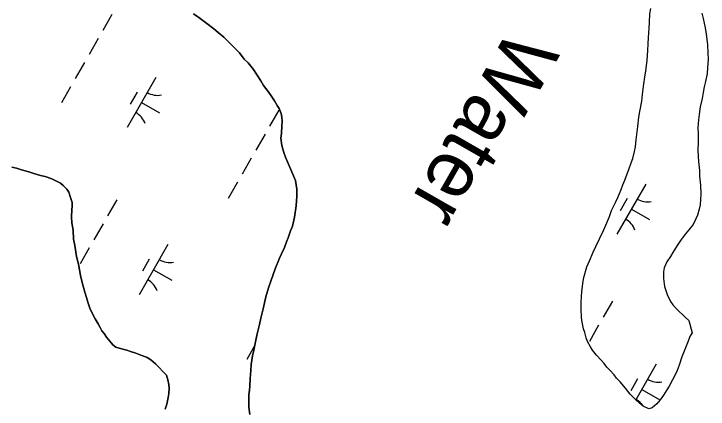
# Model space of a CAD drawing. Extents: x 3930721 to 3950824, y 220441 to 242861.
# Drawn here: x 3941538 to 3942139, y 224828 to 225170 of the extents above; entities that cross this region are included whole.
import ezdxf

# ---------------------------------------------------------------- set-up
doc = ezdxf.new("R2010")
doc.units = 0
for name, color, linetype in [('V-RIVR-IDEN', 7, 'Continuous'), ('V-TOPO-SHOR', 7, 'Continuous'), ('V-WETL-SWMP', 7, 'Continuous')]:
    doc.layers.add(name, color=color, linetype=linetype)

msp = doc.modelspace()

# ---------------------------------------------------------------- linework, layer by layer
at = {"layer": 'V-TOPO-SHOR'}
for points in [[(3941742.19, 224823.69), (3941741.55, 224829.96), (3941741.53, 224833.6), (3941741.51, 224837.25), (3941741.49, 224840.68), (3941742.08, 224844.53), (3941742.46, 224848.18), (3941742.63, 224854.85), (3941743.2, 224861.73), (3941743.58, 224866.79), (3941744.75, 224874.29), (3941745.74, 224879.35), (3941747.52, 224887.86), (3941748.7, 224893.32), (3941750.68, 224901.43), (3941751.87, 224906.9), (3941753.85, 224915), (3941755.03, 224920.07), (3941756.22, 224925.33), (3941758.6, 224933.23), (3941760.4, 224938.91), (3941764.18, 224949.65), (3941767.98, 224958.77), (3941769.78, 224962.63), (3941772.18, 224968.1), (3941774.18, 224972.97), (3941775.57, 224976.42), (3941777.56, 224982.29), (3941779.16, 224986.55), (3941780.94, 224994.25), (3941782.3, 225004.17), (3941782.87, 225012.47), (3941783.04, 225018.34), (3941781.79, 225025.81), (3941780.15, 225030.05), (3941777.48, 225035.91), (3941775.85, 225039.94), (3941773.18, 225046.2), (3941771.75, 225050.04), (3941769.89, 225056.1), (3941769.25, 225062.57), (3941769.63, 225066.62), (3941770, 225073.09), (3941770.18, 225077.34), (3941769.96, 225080.78), (3941769.34, 225084.02), (3941767.7, 225088.26), (3941766.07, 225090.88), (3941763.62, 225094.91), (3941760.76, 225099.14), (3941758.31, 225102.77), (3941754.24, 225108.21), (3941751.79, 225112.04), (3941748.12, 225117.89), (3941745.47, 225121.92), (3941740.79, 225127.56), (3941737.53, 225130.99), (3941733.25, 225136.23), (3941729.8, 225139.85), (3941726.74, 225143.07), (3941722.68, 225147.09), (3941719.83, 225149.91), (3941714.95, 225153.93), (3941711.29, 225157.15), (3941705.2, 225161.77), (3941698.29, 225166.79), (3941693.62, 225170.01)], [(3941536.31, 225037.47), (3941540.37, 225036.48), (3941544.62, 225035.28), (3941551.11, 225033.5), (3941555.36, 225032.11), (3941561.24, 225030.32), (3941565.29, 225029.32), (3941570.96, 225027.33), (3941574.01, 225025.93), (3941578.47, 225023.53), (3941580.91, 225021.52), (3941583.96, 225018.5), (3941585.79, 225015.88), (3941587.23, 225011.23), (3941588.47, 225006.79), (3941588.49, 225003.75), (3941588.3, 225000.51), (3941587.93, 224994.65), (3941588.36, 224989.39), (3941589.41, 224982.92), (3941589.85, 224975.23), (3941590.89, 224969.78), (3941592.36, 224960.27), (3941594.01, 224953.61), (3941595.89, 224943.9), (3941597.33, 224937.84), (3941599.4, 224929.36), (3941600.84, 224924.91), (3941602.28, 224920.68), (3941603.93, 224915.62)], [(3941603.93, 224915.62), (3941606.38, 224909.97), (3941608.43, 224906.34), (3941611.08, 224901.9), (3941612.71, 224898.88), (3941614.35, 224896.06), (3941616.18, 224893.64), (3941618.22, 224890.61), (3941621.07, 224886.99), (3941623.72, 224883.96), (3941626.36, 224881.96), (3941631.22, 224880.36), (3941635.88, 224879.17), (3941639.12, 224878.18), (3941643.58, 224876.59), (3941646.42, 224875.59), (3941653.52, 224872.79), (3941656.76, 224870.99), (3941660.62, 224867.57), (3941663.27, 224864.95), (3941667.74, 224860.33), (3941670.19, 224857.5), (3941671.42, 224853.67), (3941672.25, 224849.63), (3941672.47, 224846.39), (3941672.29, 224841.74), (3941671.7, 224838.29), (3941670.52, 224832.42), (3941668.93, 224828.16)]]:
    msp.add_lwpolyline(points, dxfattribs=at)
at = {"layer": 'V-WETL-SWMP'}
for p, q in [((3941623.03, 225169.54), (3941615.08, 225155.66)), ((3941693.62, 225170), (3941698.29, 225166.79)), ((3941698.29, 225166.79), (3941705.2, 225161.77)), ((3941705.2, 225161.77), (3941711.29, 225157.15)), ((3941711.29, 225157.15), (3941714.95, 225153.93)), ((3941611.11, 225148.72), (3941603.16, 225134.83)), ((3941714.95, 225153.93), (3941719.83, 225149.91)), ((3941719.83, 225149.91), (3941722.67, 225147.09)), ((3941722.67, 225147.09), (3941726.74, 225143.07)), ((3941726.74, 225143.07), (3941729.79, 225139.85)), ((3941729.79, 225139.85), (3941733.25, 225136.22)), ((3941733.25, 225136.22), (3941737.53, 225130.99)), ((3941737.53, 225130.99), (3941740.78, 225127.56)), ((3941599.18, 225127.89), (3941591.23, 225114.01)), ((3941740.78, 225127.56), (3941745.47, 225121.92)), ((3941745.47, 225121.92), (3941748.12, 225117.89)), ((3941661.01, 225115.04), (3941636.16, 225071.66)), ((3941748.12, 225117.89), (3941751.79, 225112.04)), ((3941587.25, 225107.06), (3941579.3, 225093.18)), ((3941751.79, 225112.04), (3941754.24, 225108.21)), ((3941754.24, 225108.21), (3941758.31, 225102.77)), ((3941644.87, 225102.39), (3941638.9, 225091.98)), ((3941758.31, 225102.77), (3941760.76, 225099.14)), ((3941760.76, 225099.14), (3941763.62, 225094.91)), ((3941763.62, 225094.91), (3941766.06, 225090.88)), ((3941648.58, 225093.35), (3941664.2, 225084.4)), ((3941766.06, 225090.88), (3941767.7, 225088.26)), ((3941767.38, 225086.88), (3941759.42, 225072.99)), ((3941767.7, 225088.26), (3941769.34, 225084.02)), ((3941769.34, 225084.02), (3941769.96, 225080.78)), ((3941769.96, 225080.78), (3941770.18, 225077.34)), ((3941770.18, 225077.34), (3941770, 225073.09)), ((3941770, 225073.09), (3941769.63, 225066.62)), ((3941755.45, 225066.05), (3941747.5, 225052.17)), ((3941769.63, 225066.62), (3941769.25, 225062.57)), ((3941769.25, 225062.57), (3941769.89, 225056.1)), ((3941769.89, 225056.1), (3941771.74, 225050.04)), ((3941771.74, 225050.04), (3941773.18, 225046.2)), ((3941743.52, 225045.22), (3941735.57, 225031.34)), ((3941773.18, 225046.2), (3941775.84, 225039.94)), ((3941540.37, 225036.48), (3941536.31, 225037.47)), ((3941544.62, 225035.28), (3941540.37, 225036.48)), ((3941551.1, 225033.5), (3941544.62, 225035.28)), ((3941775.84, 225039.94), (3941777.48, 225035.91)), ((3941777.48, 225035.91), (3941780.14, 225030.05)), ((3941555.36, 225032.1), (3941551.1, 225033.5)), ((3941561.24, 225030.31), (3941555.36, 225032.1)), ((3941565.29, 225029.32), (3941561.24, 225030.31)), ((3941570.96, 225027.33), (3941565.29, 225029.32)), ((3941780.14, 225030.05), (3941781.78, 225025.81)), ((3941574.01, 225025.93), (3941570.96, 225027.33)), ((3941578.47, 225023.53), (3941574.01, 225025.93)), ((3941580.91, 225021.52), (3941578.47, 225023.53)), ((3941731.59, 225024.4), (3941723.64, 225010.51)), ((3941781.78, 225025.81), (3941783.04, 225018.34)), ((3942084.88, 225022.92), (3942060.03, 224979.53)), ((3941583.96, 225018.5), (3941580.91, 225021.52)), ((3941585.79, 225015.88), (3941583.96, 225018.5)), ((3941783.04, 225018.34), (3941782.87, 225012.47)), ((3941587.23, 225011.23), (3941585.79, 225015.88)), ((3941588.47, 225006.79), (3941587.23, 225011.23)), ((3941782.87, 225012.47), (3941782.3, 225004.17)), ((3942068.74, 225010.27), (3942062.78, 224999.86)), ((3941588.49, 225003.75), (3941588.47, 225006.79)), ((3941627.21, 225009.33), (3941619.26, 224995.44)), ((3941587.93, 224994.65), (3941588.3, 225000.51)), ((3941588.3, 225000.51), (3941588.49, 225003.75)), ((3941782.3, 225004.17), (3941780.94, 224994.25)), ((3942072.46, 225001.23), (3942088.08, 224992.28)), ((3941588.36, 224989.39), (3941587.93, 224994.65)), ((3941780.94, 224994.25), (3941779.16, 224986.55)), ((3941589.41, 224982.92), (3941588.36, 224989.39)), ((3941615.29, 224988.5), (3941607.33, 224974.62)), ((3941779.16, 224986.55), (3941777.56, 224982.29)), ((3941589.85, 224975.23), (3941589.41, 224982.92)), ((3941777.56, 224982.29), (3941775.57, 224976.42)), ((3941590.89, 224969.78), (3941589.85, 224975.23)), ((3941775.57, 224976.42), (3941774.17, 224972.97)), ((3941592.36, 224960.28), (3941590.89, 224969.78)), ((3941671.48, 224970.49), (3941646.63, 224927.1)), ((3941774.17, 224972.97), (3941772.18, 224968.1)), ((3941603.36, 224967.67), (3941595.41, 224953.79)), ((3941769.78, 224962.63), (3941767.98, 224958.77)), ((3941772.18, 224968.1), (3941769.78, 224962.63)), ((3941594.01, 224953.61), (3941592.36, 224960.28)), ((3941655.34, 224957.83), (3941649.38, 224947.42)), ((3941767.98, 224958.77), (3941764.18, 224949.65)), ((3941595.88, 224943.91), (3941594.01, 224953.61)), ((3941659.06, 224948.79), (3941674.68, 224939.85)), ((3941764.18, 224949.65), (3941760.39, 224938.91)), ((3941597.33, 224937.84), (3941595.88, 224943.91)), ((3941760.39, 224938.91), (3941758.6, 224933.23)), ((3941599.4, 224929.36), (3941597.33, 224937.84)), ((3941758.6, 224933.23), (3941756.22, 224925.33)), ((3941600.84, 224924.92), (3941599.4, 224929.36)), ((3941602.28, 224920.67), (3941600.84, 224924.92)), ((3941603.92, 224915.62), (3941602.28, 224920.67)), ((3941756.22, 224925.33), (3941755.03, 224920.06)), ((3942056.06, 224921.54), (3942048.11, 224907.66)), ((3941606.38, 224909.97), (3941603.92, 224915.62)), ((3941753.84, 224915), (3941751.86, 224906.9)), ((3941755.03, 224920.06), (3941753.84, 224915)), ((3941608.42, 224906.34), (3941606.38, 224909.97)), ((3941611.08, 224901.91), (3941608.42, 224906.34)), ((3941751.86, 224906.9), (3941750.68, 224901.43)), ((3941612.71, 224898.88), (3941611.08, 224901.91)), ((3941614.35, 224896.06), (3941612.71, 224898.88)), ((3941750.68, 224901.43), (3941748.7, 224893.33)), ((3942044.13, 224900.72), (3942036.18, 224886.83)), ((3941616.18, 224893.64), (3941614.35, 224896.06)), ((3941618.22, 224890.61), (3941616.18, 224893.64)), ((3941621.07, 224886.99), (3941618.22, 224890.61)), ((3941748.7, 224893.33), (3941747.51, 224887.86)), ((3941623.72, 224883.97), (3941621.07, 224886.99)), ((3941747.51, 224887.86), (3941745.74, 224879.35)), ((3941626.36, 224881.96), (3941623.72, 224883.97)), ((3941631.22, 224880.36), (3941626.36, 224881.96)), ((3941635.88, 224879.17), (3941631.22, 224880.36)), ((3941639.12, 224878.18), (3941635.88, 224879.17)), ((3941643.58, 224876.59), (3941639.12, 224878.18)), ((3941746.47, 224882.86), (3941739.75, 224871.12)), ((3941745.74, 224879.35), (3941744.75, 224874.29)), ((3941646.42, 224875.59), (3941643.58, 224876.59)), ((3941653.51, 224872.79), (3941646.42, 224875.59)), ((3941656.76, 224870.99), (3941653.51, 224872.79)), ((3941744.75, 224874.29), (3941743.58, 224866.79)), ((3941660.62, 224867.57), (3941656.76, 224870.99)), ((3941663.27, 224864.95), (3941660.62, 224867.57)), ((3941743.58, 224866.79), (3941743.2, 224861.73)), ((3942094.03, 224867.04), (3942076.43, 224836.32)), ((3941667.74, 224860.33), (3941663.27, 224864.95)), ((3941670.19, 224857.51), (3941667.74, 224860.33)), ((3941743.2, 224861.73), (3941742.63, 224854.85)), ((3941671.42, 224853.67), (3941670.19, 224857.51)), ((3941742.63, 224854.85), (3941742.46, 224848.18)), ((3942077.89, 224854.39), (3942071.93, 224843.98)), ((3941672.25, 224849.63), (3941671.42, 224853.67)), ((3941672.47, 224846.39), (3941672.25, 224849.63)), ((3941742.46, 224848.18), (3941742.08, 224844.53)), ((3941672.29, 224841.74), (3941672.47, 224846.39)), ((3941742.08, 224844.53), (3941741.49, 224840.69)), ((3942081.6, 224845.35), (3942097.22, 224836.41)), ((3941670.52, 224832.42), (3941671.7, 224838.29)), ((3941671.7, 224838.29), (3941672.29, 224841.74)), ((3941741.49, 224840.69), (3941741.51, 224837.25)), ((3941741.51, 224837.25), (3941741.53, 224833.6)), ((3941668.92, 224828.16), (3941670.52, 224832.42)), ((3941741.53, 224833.6), (3941741.55, 224829.96)), ((3941741.55, 224829.96), (3941742.19, 224823.69))]:
    msp.add_line(p, q, dxfattribs=at)
for points in [[(3942063.61, 225018.05), (3942065.21, 225022.11), (3942066.8, 225026.36), (3942068.79, 225031.83), (3942070.19, 225035.48), (3942072.39, 225041.36), (3942073.78, 225045.01), (3942075.17, 225050.89), (3942076.16, 225054.94), (3942076.73, 225061.21), (3942077.11, 225065.67), (3942078.09, 225072.75), (3942079.06, 225080.65), (3942079.84, 225085.71), (3942081.41, 225094.42), (3942082.19, 225100.29), (3942083.36, 225109.6), (3942084.14, 225115.27), (3942084.92, 225120.74), (3942086.08, 225129.65), (3942086.64, 225138.35), (3942087.02, 225144.01), (3942087.39, 225149.68), (3942087.76, 225157.57), (3942088.13, 225162.63), (3942088.5, 225169.92), (3942089.29, 225174.58)], [(3942133.41, 225170.76), (3942134.65, 225165.91), (3942136.31, 225157.83), (3942137.15, 225152.37)], [(3942137.15, 225152.37), (3942138.21, 225143.68), (3942138.65, 225135.99), (3942138.88, 225130.93), (3942138.31, 225123.24), (3942137.93, 225118.59), (3942136.56, 225111.5), (3942135.57, 225106.84), (3942134.58, 225101.98), (3942133.6, 225096.92), (3942132.02, 225089.63), (3942131.04, 225082.95), (3942130.46, 225078.49), (3942130.09, 225071.61), (3942130.32, 225066.55), (3942130.36, 225059.07), (3942129.99, 225051.99), (3942130.22, 225046.93), (3942130.65, 225042.28), (3942131.3, 225034.59), (3942131.52, 225029.74), (3942132.17, 225021.85), (3942132.62, 225014.17), (3942131.86, 225004.86), (3942131.27, 225001.21), (3942129.68, 224995.94), (3942128.28, 224992.7), (3942125.88, 224987.83), (3942122.06, 224983.36), (3942119.45, 224979.7), (3942115.03, 224974.02), (3942112.22, 224969.75), (3942108.41, 224963.66), (3942106.2, 224960.21), (3942103.19, 224955.54), (3942100.99, 224950.47), (3942100.2, 224947.03), (3942100.23, 224941.16), (3942101.28, 224934.29), (3942103.34, 224927.42), (3942106.2, 224921.37), (3942108.24, 224918.54), (3942111.7, 224914.72), (3942114.14, 224912.51), (3942116.58, 224910.09), (3942119.22, 224907.48), (3942122.27, 224904.86), (3942124.96, 224894.15), (3942123.35, 224891.51), (3942121.16, 224885.64), (3942118.16, 224878.34), (3942116.16, 224873.47), (3942113.77, 224866.38), (3942111.98, 224861.71), (3942110.18, 224857.25), (3942108.18, 224853.6), (3942105.17, 224848.12), (3942103.17, 224844.88), (3942100.16, 224840.21), (3942097.34, 224836.35), (3942094.53, 224832.89), (3942090.5, 224829.43), (3942087.67, 224828.4), (3942082.81, 224830.81), (3942079.35, 224833.62), (3942076.3, 224836.44), (3942071.42, 224841.27), (3942067.35, 224846.3), (3942062.87, 224851.74), (3942059.61, 224855.17), (3942057.58, 224857.99), (3942053.91, 224861.81), (3942051.27, 224864.63), (3942048.82, 224867.65), (3942046.38, 224870.47), (3942042.31, 224874.9), (3942038.85, 224879.33), (3942037.01, 224882.16), (3942034.56, 224886.8), (3942033.33, 224890.03), (3942032.09, 224894.47), (3942031.06, 224897.7), (3942030.02, 224903.36), (3942029.39, 224907.61), (3942029.15, 224915.09), (3942029.12, 224920.76), (3942029.48, 224929.86), (3942030.85, 224938.97), (3942031.44, 224942.21), (3942033.81, 224951.33), (3942036.22, 224956.4), (3942039.41, 224963.9), (3942041.61, 224968.77), (3942045.02, 224975.47), (3942048.42, 224982.77), (3942050.42, 224987.23), (3942053.41, 224994.93), (3942055.41, 225000), (3942058.61, 225006.9), (3942060.81, 225011.36), (3942063.61, 225018.05)]]:
    msp.add_lwpolyline(points, dxfattribs=at)
for centre, start, end in [((3941662.51, 225117.2), 239.42788, 280.97154), ((3941635.06, 225069.26), 19.42788, 60.97154), ((3942086.39, 225025.08), 239.42788, 280.97154), ((3942058.93, 224977.14), 19.42788, 60.97154), ((3941672.99, 224972.64), 239.42788, 280.97154), ((3941645.53, 224924.71), 19.42788, 60.97154), ((3942095.54, 224869.2), 239.42788, 280.97154), ((3942068.08, 224821.26), 32.52439, 60.97154)]:
    msp.add_arc(centre, 17.62, start, end, dxfattribs=at)

# ---------------------------------------------------------------- texts
at = {"layer": 'V-RIVR-IDEN'}
msp.add_text('Water', height=50, rotation=240.19966, dxfattribs=at).set_placement((3941967.59, 225159.56))

doc.saveas('drawing.dxf')
